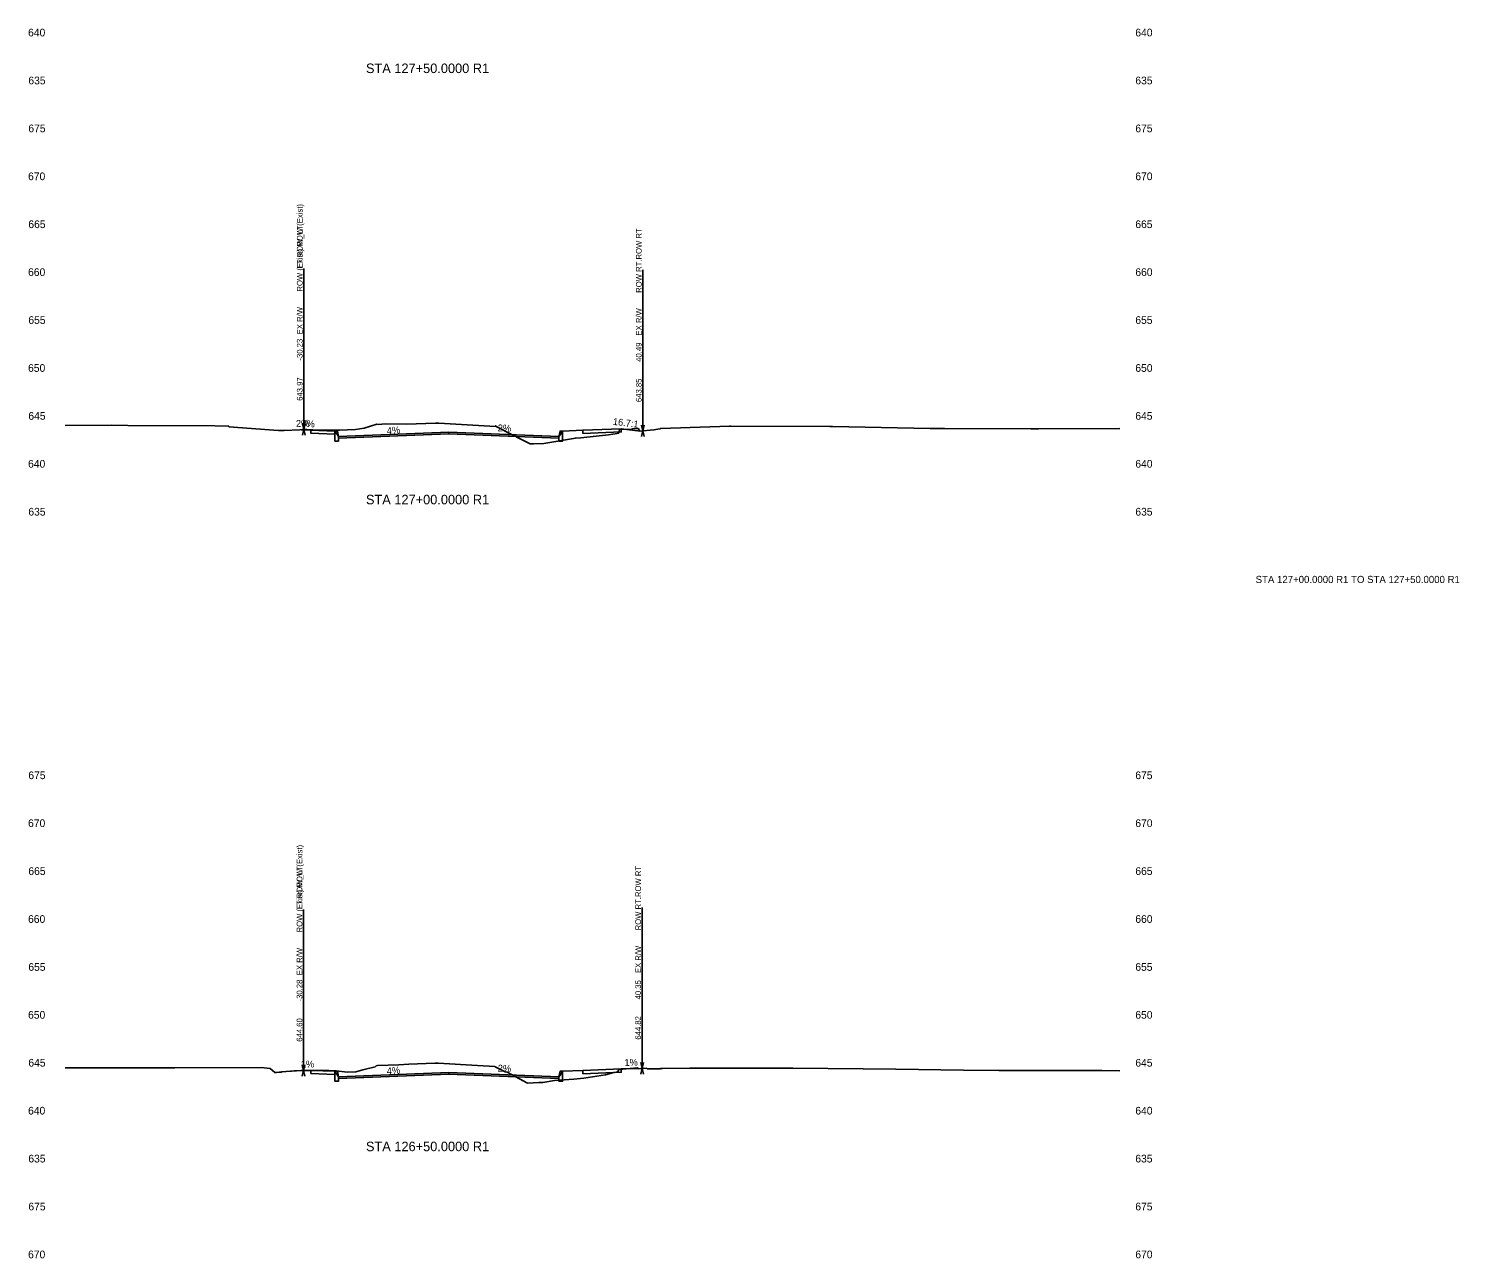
# Model space of a CAD drawing. Extents: x 2 to 741, y 16 to 2207.
# Drawn here: x 2.4 to 300.8, y 1675 to 1931.6 of the extents above; entities that cross this region are included whole.
import ezdxf

# ---------------------------------------------------------------- set-up
doc = ezdxf.new("R2010")
doc.units = 0
for name, color, linetype in [('BORD_text_large_2', 7, 'Continuous'), ('Draft_XS_Feature_Name', 7, 'Continuous'), ('Draft_XS_Label', 7, 'Continuous'), ('Draft_XS_Point_Label_Indicator', 7, 'Continuous'), ('Draft_XS_Terminator', 7, 'Continuous'), ('Draft_XS_Text', 7, 'Continuous'), ('E_ROW', 7, 'Continuous'), ('E_Terrain_Exterior', 7, 'Continuous'), ('E_Terrain_Points_Low', 7, 'Continuous'), ('Grade_Veg_Grass', 7, 'Continuous'), ('P_XS_Sections', 7, 'Continuous'), ('Road_Curb', 7, 'Continuous'), ('Road_Pave_Asphalt', 7, 'Continuous'), ('Road_Sidewalk', 7, 'Continuous'), ('Terrain_Design', 7, 'Continuous')]:
    doc.layers.add(name, color=color, linetype=linetype)

msp = doc.modelspace()

# ---------------------------------------------------------------- linework, layer by layer
at = {"layer": 'Draft_XS_Terminator'}
for p, q in [((59.77, 1847.95), (59.77, 1869.95)), ((59.77, 1847.95), (59.77, 1869.95)), ((130.49, 1847.69), (130.49, 1869.69)), ((59.72, 1714.2), (59.72, 1736.2)), ((59.72, 1714.2), (59.72, 1736.2)), ((130.35, 1714.63), (130.35, 1736.63))]:
    msp.add_line(p, q, dxfattribs=at)
at = {"layer": 'E_ROW'}
for p, q in [((59.77, 1847.95), (59.77, 1881.55)), ((59.77, 1847.95), (59.77, 1881.55)), ((130.49, 1847.69), (130.49, 1881.29)), ((59.47, 1846.75), (60.07, 1849.15)), ((59.47, 1849.15), (60.07, 1846.75)), ((59.47, 1846.75), (60.07, 1849.15)), ((59.47, 1849.15), (60.07, 1846.75)), ((130.19, 1846.49), (130.79, 1848.89)), ((130.19, 1848.89), (130.79, 1846.49)), ((59.72, 1714.2), (59.72, 1747.8)), ((59.72, 1714.2), (59.72, 1747.8)), ((130.35, 1714.63), (130.35, 1748.23)), ((59.42, 1713), (60.02, 1715.4)), ((59.42, 1715.4), (60.02, 1713)), ((59.42, 1713), (60.02, 1715.4)), ((59.42, 1715.4), (60.02, 1713)), ((130.05, 1713.43), (130.65, 1715.83)), ((130.05, 1715.83), (130.65, 1713.43))]:
    msp.add_line(p, q, dxfattribs=at)
at = {"layer": 'E_Terrain_Exterior'}
for points in [[(10, 1848.78), (19.71, 1848.88), (23.04, 1848.78), (41.19, 1848.73), (43.97, 1848.65), (44.12, 1848.65), (44.15, 1848.53), (54.48, 1847.74), (55.65, 1847.78), (58.95, 1847.91), (59.53, 1847.94), (60.13, 1847.96), (60.19, 1847.96), (60.21, 1847.96), (60.22, 1847.96), (60.44, 1847.97), (62.89, 1847.8), (67.2, 1847.81), (70.59, 1847.94), (72.37, 1848.21), (74.98, 1849.07), (75.34, 1849.03), (75.34, 1849.04), (75.35, 1849.04), (76.77, 1849.12), (81.19, 1849.06), (87.25, 1849.28), (87.32, 1849.27), (87.59, 1849.26), (87.66, 1849.26), (87.93, 1849.29), (90.27, 1849.14), (99.77, 1848.6), (99.79, 1848.76), (100.06, 1848.52), (105.62, 1845.65), (105.74, 1845.63), (106.99, 1844.97), (107.69, 1845), (109.82, 1845.03), (116.42, 1846.17), (117.59, 1846.24), (123.35, 1846.87), (125.14, 1847.15), (125.45, 1847.17), (125.52, 1847.43), (125.65, 1847.95), (128.23, 1848.05), (128.36, 1848.07), (129.56, 1848.17), (129.83, 1847.64), (132.79, 1847.89), (134.02, 1848.1), (134.02, 1848.1), (134.03, 1848.1), (134.05, 1848.11), (134.07, 1848.12), (134.07, 1848.12), (134.08, 1848.12), (134.08, 1848.12), (134.11, 1848.14), (134.24, 1848.2), (134.25, 1848.2), (148.6, 1848.63), (148.6, 1848.63), (148.61, 1848.63), (148.87, 1848.63), (169.53, 1848.62), (170.08, 1848.61), (190.46, 1848.19), (191.03, 1848.18), (191.56, 1848.17), (193.45, 1848.16), (211.39, 1848.08), (212.78, 1848.09), (213.05, 1848.09), (230, 1848.14)], [(10, 1714.73), (11.06, 1714.74), (11.4, 1714.75), (11.84, 1714.75), (29.95, 1714.78), (30.65, 1714.78), (32.88, 1714.76), (50.87, 1714.81), (52.75, 1714.61), (53.73, 1713.76), (54.07, 1713.79), (54.61, 1713.83), (55.08, 1713.87), (55.16, 1713.88), (57.02, 1714.04), (57.2, 1714.06), (57.79, 1714.11), (57.9, 1714.12), (57.99, 1714.13), (58, 1714.13), (58.22, 1714.15), (59.32, 1714.2), (62.68, 1714.18), (63.47, 1714.29), (66.52, 1714.12), (68.79, 1713.83), (70.6, 1713.93), (72.09, 1714.34), (74.63, 1714.99), (74.86, 1715.14), (75.18, 1715.25), (79.62, 1715.36), (81.71, 1715.53), (87.13, 1715.72), (87.37, 1715.7), (87.47, 1715.7), (87.72, 1715.7), (87.82, 1715.71), (96.02, 1715.2), (99.59, 1715), (99.6, 1715.06), (99.7, 1714.97), (101.79, 1713.89), (102.19, 1713.81), (106.43, 1711.56), (108.82, 1711.66), (109.62, 1711.68), (112.09, 1712.1), (116.07, 1712.36), (118.22, 1712.59), (122.72, 1713.28), (123.98, 1713.64), (125.19, 1713.89), (125.27, 1713.91), (125.27, 1713.91), (125.48, 1714.43), (125.51, 1714.43), (129.41, 1714.76), (129.51, 1714.56), (131.25, 1714.71), (131.41, 1714.57), (134.1, 1714.53), (134.11, 1714.53), (134.12, 1714.54), (134.13, 1714.54), (134.15, 1714.55), (134.16, 1714.55), (134.16, 1714.56), (134.2, 1714.58), (134.22, 1714.59), (134.24, 1714.6), (134.59, 1714.6), (140.29, 1714.7), (155.51, 1714.7), (161.78, 1714.67), (176.44, 1714.55), (183.26, 1714.45), (197.37, 1714.28), (204.74, 1714.2), (218.3, 1714.17), (226.22, 1714.16), (230, 1714.14)]]:
    msp.add_lwpolyline(points, dxfattribs=at)
at = {"layer": 'Grade_Veg_Grass'}
for points in [[(59.25, 1847.92), (61.25, 1847.84), (61.25, 1847.84)], [(113.75, 1847.64), (118, 1847.81)], [(130, 1847.65), (130, 1847.65), (126, 1848.13)], [(59.25, 1714.2), (61.25, 1714.22), (61.25, 1714.22)], [(113.75, 1714.02), (118, 1714.19)], [(130, 1714.6), (126, 1714.51), (126, 1714.51)]]:
    msp.add_lwpolyline(points, dxfattribs=at)
at = {"layer": 'Road_Curb'}
for points in [[(67, 1846.47), (67, 1845.56), (66.25, 1845.56), (66.25, 1847.64), (66.77, 1847.64), (67, 1846.47)], [(113, 1846.47), (113, 1845.56), (113.75, 1845.56), (113.75, 1847.64), (113.23, 1847.64), (113, 1846.47)], [(67, 1712.85), (67, 1711.94), (66.25, 1711.94), (66.25, 1714.02), (66.77, 1714.02), (67, 1712.85)], [(113, 1712.85), (113, 1711.94), (113.75, 1711.94), (113.75, 1714.02), (113.23, 1714.02), (113, 1712.85)]]:
    msp.add_lwpolyline(points, dxfattribs=at)
at = {"layer": 'Road_Pave_Asphalt'}
for points in [[(90, 1847.39), (90, 1847.06), (67, 1846.14), (67, 1846.47), (90, 1847.39)], [(90, 1847.39), (90, 1847.06), (113, 1846.14), (113, 1846.47), (90, 1847.39)], [(90, 1713.77), (90, 1713.44), (67, 1712.52), (67, 1712.85), (90, 1713.77)], [(90, 1713.77), (90, 1713.44), (113, 1712.52), (113, 1712.85), (90, 1713.77)]]:
    msp.add_lwpolyline(points, dxfattribs=at)
at = {"layer": 'Road_Sidewalk'}
for points in [[(66.25, 1847.64), (66.25, 1846.97), (61.25, 1847.17), (61.25, 1847.84), (66.25, 1847.64)], [(118, 1847.81), (118, 1847.14), (126, 1847.46), (126, 1848.13), (118, 1847.81)], [(66.25, 1714.02), (66.25, 1713.35), (61.25, 1713.55), (61.25, 1714.22), (66.25, 1714.02)], [(118, 1714.19), (118, 1713.52), (126, 1713.84), (126, 1714.51), (118, 1714.19)]]:
    msp.add_lwpolyline(points, dxfattribs=at)
at = {"layer": 'Terrain_Design'}
for points in [[(59.25, 1847.92), (59.25, 1847.92), (61.25, 1847.84), (66.25, 1847.64), (66.77, 1847.64), (67, 1846.47), (90, 1847.39), (113, 1846.47), (113.23, 1847.64), (113.75, 1847.64), (118, 1847.81), (126, 1848.13), (130, 1847.65)], [(59.25, 1847.92), (61.25, 1847.84), (66.25, 1847.64), (66.77, 1846.83), (67, 1846.47), (90, 1847.39), (113, 1846.47), (113.23, 1846.83), (113.75, 1847.64), (118, 1847.81), (126, 1848.13), (130, 1847.65)], [(59.25, 1714.2), (61.25, 1714.22), (66.25, 1714.02), (66.77, 1714.02), (67, 1712.85), (90, 1713.77), (113, 1712.85), (113.23, 1714.02), (113.75, 1714.02), (118, 1714.19), (126, 1714.51), (130, 1714.6)], [(59.25, 1714.2), (61.25, 1714.22), (66.25, 1714.02), (66.77, 1713.21), (67, 1712.85), (90, 1713.77), (113, 1712.85), (113.23, 1713.21), (113.75, 1714.02), (118, 1714.19), (126, 1714.51), (130, 1714.6)]]:
    msp.add_lwpolyline(points, dxfattribs=at)

# ---------------------------------------------------------------- texts
at = {"layer": 'BORD_text_large_2'}
msp.add_text('STA 127+00.0000 R1 TO STA 127+50.0000 R1', height=1.5, dxfattribs=at).set_placement((258.32, 1815.92))
at = {"layer": 'Draft_XS_Feature_Name'}
for s, p in [('ROW (Exist).ROW (Exist)', (59.53, 1876.75)), ('ROW_LT.ROW_LT', (59.53, 1876.75)), ('ROW RT.ROW RT', (130.25, 1876.49)), ('ROW (Exist).ROW (Exist)', (59.48, 1743)), ('ROW_LT.ROW_LT', (59.48, 1743)), ('ROW RT.ROW RT', (130.11, 1743.43))]:
    msp.add_text(s, height=1.2, rotation=90, dxfattribs=at).set_placement(p)
at = {"layer": 'Draft_XS_Label'}
for s, p in [('-30.23', (59.53, 1862.35)), ('-30.23', (59.53, 1862.35)), ('40.49', (130.25, 1862.09)), ('643.97', (59.53, 1853.95)), ('643.97', (59.53, 1853.95)), ('643.85', (130.25, 1853.69)), ('-30.28', (59.48, 1728.6)), ('-30.28', (59.48, 1728.6)), ('40.35', (130.11, 1729.03)), ('644.60', (59.48, 1720.2)), ('644.60', (59.48, 1720.2)), ('644.82', (130.11, 1720.63))]:
    msp.add_text(s, height=1.2, rotation=90, dxfattribs=at).set_placement(p)
at = {"layer": 'Draft_XS_Point_Label_Indicator'}
for p in [(59.24, 1847.91), (61.24, 1847.83), (66.24, 1847.63), (66.76, 1847.63), (113.22, 1847.63), (113.74, 1847.63), (117.99, 1847.8), (125.99, 1848.12), (129.99, 1847.64), (66.99, 1846.46), (66.99, 1845.54), (112.99, 1846.46), (112.99, 1845.54), (59.24, 1714.19), (61.24, 1714.21), (66.24, 1714.01), (66.76, 1714.01), (113.22, 1714.01), (113.74, 1714.01), (117.99, 1714.18), (125.99, 1714.5), (129.99, 1714.59), (66.99, 1712.84), (66.99, 1711.92), (112.99, 1712.84), (112.99, 1711.92)]:
    msp.add_text('X', height=0.024, dxfattribs=at).set_placement(p)
at = {"layer": 'Draft_XS_Text'}
for s, height, p in [('640', 1.608, (2.26, 1930)), ('640', 1.608, (233.22, 1930)), ('STA 127+50.0000 R1', 1.992, (72.74, 1922.35)), ('635', 1.608, (2.32, 1920)), ('635', 1.608, (233.22, 1920)), ('675', 1.608, (2.32, 1910)), ('675', 1.608, (233.22, 1910)), ('670', 1.608, (2.26, 1900)), ('670', 1.608, (233.22, 1900)), ('665', 1.608, (2.32, 1890)), ('665', 1.608, (233.22, 1890)), ('660', 1.608, (2.26, 1880)), ('660', 1.608, (233.22, 1880)), ('655', 1.608, (2.32, 1870)), ('655', 1.608, (233.22, 1870)), ('650', 1.608, (2.26, 1860)), ('650', 1.608, (233.22, 1860)), ('645', 1.608, (2.32, 1850)), ('645', 1.608, (233.22, 1850)), ('640', 1.608, (2.26, 1840)), ('640', 1.608, (233.22, 1840)), ('STA 127+00.0000 R1', 1.992, (72.74, 1832.35)), ('635', 1.608, (2.32, 1830)), ('635', 1.608, (233.22, 1830)), ('675', 1.608, (2.32, 1775)), ('675', 1.608, (233.22, 1775)), ('670', 1.608, (2.26, 1765)), ('670', 1.608, (233.22, 1765)), ('665', 1.608, (2.32, 1755)), ('665', 1.608, (233.22, 1755)), ('660', 1.608, (2.26, 1745)), ('660', 1.608, (233.22, 1745)), ('655', 1.608, (2.32, 1735)), ('655', 1.608, (233.22, 1735)), ('650', 1.608, (2.26, 1725)), ('650', 1.608, (233.22, 1725)), ('645', 1.608, (2.32, 1715)), ('645', 1.608, (233.22, 1715)), ('640', 1.608, (2.26, 1705)), ('640', 1.608, (233.22, 1705)), ('STA 126+50.0000 R1', 1.992, (72.74, 1697.35)), ('635', 1.608, (2.32, 1695)), ('635', 1.608, (233.22, 1695)), ('675', 1.608, (2.32, 1685)), ('675', 1.608, (233.22, 1685)), ('670', 1.608, (2.26, 1675)), ('670', 1.608, (233.22, 1675))]:
    msp.add_text(s, height=height, dxfattribs=at).set_placement(p)
for s, rotation, p in [('2%', 2.267, (58.17, 1848.48)), ('4%', 355.9208, (59.24, 1848.58)), ('4%', 4.5657, (77.14, 1846.97)), ('2%', 357.7094, (100.21, 1847.59)), ('16.7:1', 353.1775, (124.19, 1848.95)), ('1%', 0.7539, (59.16, 1714.79)), ('1%', 1.3376, (126.67, 1715.13)), ('4%', 4.5657, (77.14, 1713.35)), ('2%', 357.7094, (100.21, 1713.97))]:
    msp.add_text(s, height=1.44, rotation=rotation, dxfattribs=at).set_placement(p)
at = {"layer": 'E_ROW'}
for p in [(59.53, 1867.83), (59.53, 1867.83), (130.25, 1867.58), (130.11, 1734.52), (59.48, 1734.08), (59.48, 1734.08)]:
    msp.add_text('EX R/W', height=1.2, rotation=90, dxfattribs=at).set_placement(p)
at = {"layer": 'E_Terrain_Points_Low'}
for p in [(89.99, 1847.38), (89.99, 1713.76)]:
    msp.add_text('X', height=0.024, dxfattribs=at).set_placement(p)
at = {"layer": 'P_XS_Sections'}
for p in [(10, 1920), (10, 1830), (10, 1695)]:
    msp.add_text('-', height=0.0001, dxfattribs=at).set_placement(p)

doc.saveas('drawing.dxf')
